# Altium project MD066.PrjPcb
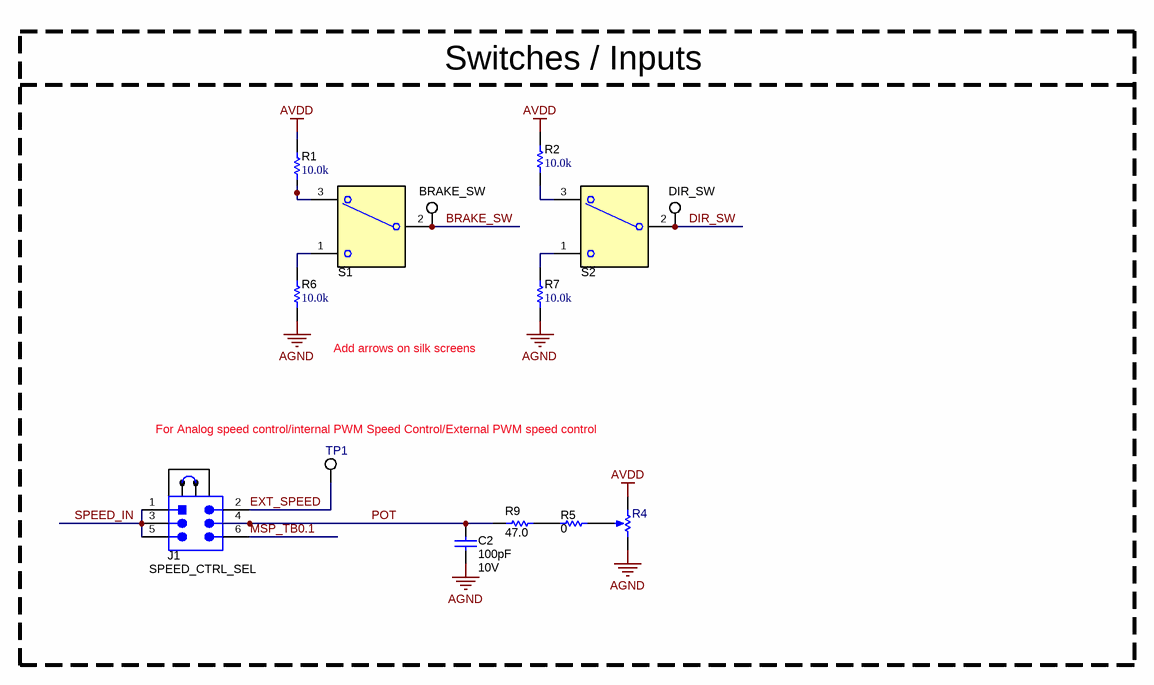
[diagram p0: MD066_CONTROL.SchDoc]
CopyrightYear: 2022; PCB_Layout: Vishnu Balaraj; PCB_Rev: A1; PRJ_Customer: Public Release; PRJ_Engineer: Vishnu Balaraj; PRJ_Number: MD066; PRJ_Title: MCx8317AEVM; ProjectVariant: EVM_Orderable; SCH_Rev: A1; TechSupport: http://www.ti.com/support; TID: N/A
5 sheets, 159 parts. Net scope: global (net labels, ports and power ports of the same name join across sheets).
Board file: MD066.PcbDoc
Sheets:
  MD066_CONTROL.SchDoc
  MD066_DRIVER.SchDoc
  MD066_HARDWARE.SchDoc
  MD066_INTERFACE.SchDoc
  MD066_POWER_AND_CONNECTORS.SchDoc

## Sheet MD066_CONTROL.SchDoc
size 431 x 279 mm; Date: Not shown in title block; ApprovedBy: Not shown in title block; CheckedBy: Not shown in title block; Author: Not shown in title block; CompanyName: Not shown in title block; Engineer: Not shown in title block; Organization: Not shown in title block; Address1: Not shown in title block; Address2: Not shown in title block; Address3: Not shown in title block; Address4: Not shown in title block; DocumentNumber: 1; Revision: Use project parameter SCH_Rev; SheetNumber: 2; SheetTotal: 5; PageSetup: Record=PageOptions¦CenterHorizontal=True¦CenterVertical=True¦PrintScale=1.00¦XCorrection=1.00¦YCorrection=1.00¦PrintKind=0¦BorderSize=5000000¦LeftOffset=0¦BottomOffset=0¦Orientation=2¦PaperLength=1000¦PaperWidth=1000¦Scale=100¦PaperSource=15¦PrintQuality=600¦MediaType=1¦DitherType=10¦PaperKind=Letter¦PrintScaleMode=1

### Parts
C2  Cap_F: 100pF  VDC_V: 10V  [0603]  (hidden comment: 0603ZC101KAT2A)
J1  SPEED_CTRL_SEL  [TSW-103-07-G-D]
R1  ValueDisplayed: 10.0k  [0603]  (hidden comment: RNCF0603TKY10K0)
R2  ValueDisplayed: 10.0k  [0603]  (hidden comment: RNCF0603TKY10K0)
R4  3352T-1-253LF  [Bourns_3352T]  (value not drawn)
R5  ValueDisplayed: 0  [0603L]  (hidden comment: ERJ-3GEY0R00V)
R6  ValueDisplayed: 10.0k  [0603]  (hidden comment: RNCF0603TKY10K0)
R7  ValueDisplayed: 10.0k  [0603]  (hidden comment: RNCF0603TKY10K0)
R9  ValueDisplayed: 47.0  [0603]  (hidden comment: RT0603BRD0747RL)
S1  SW_SPDT_COM2_1_3  [SW_B12AP]  (value not drawn)
S2  SW_SPDT_COM2_1_3  [SW_B12AP]  (value not drawn)
SH-J1  SNT-100-BK-G  [SNT-100-BK-G]  (value not drawn)
TP1  EXT_SPEED  [Keystone5002]  (value not drawn)
TP2  BRAKE_SW  [Keystone5002]
TP3  DIR_SW  [Keystone5002]

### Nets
AGND: C2.2 R4.3(CW) R6.1 R7.1
AVDD: R1.2 R2.2 R4.1(CCW)
BRAKE_SW: S1.2(COM) TP2.1
DIR_SW: S2.2(COM) TP3.1
EXT_SPEED: J1.2 TP1.1
MSP_TB0.1: J1.6
POT: C2.1 J1.4 R9.1
SPEED_IN: J1.1 J1.3 J1.5
NetR1_1: R1.1 S1.3
NetR2_1: R2.1 S2.3
NetR4_2: R4.2(WIPER) R5.2
NetR5_1: R5.1 R9.2
NetR6_2: R6.2 S1.1
NetR7_2: R7.2 S2.1

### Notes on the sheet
- Switches / Inputs
- Add arrows on silk screens
- For Analog speed control/internal PWM Speed Control/External PWM speed control

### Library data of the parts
C2 = CMP-0006812-1: CAP, CERM, 100 pF, 10 V, +/- 10%, X7R, 0603; Manufacturer: AVX; TaMin_C: -55°C; Polarized: N; SizeAreaWB_mm2: 4.68; Value1: Unknown; U/M: EA; Value: 100pF; TaMax_C: 125°C; SizeZ_mm: 1; SizeX_mm: 1.6; SizeY_mm: 0.8; SizeArea_mm2: 1.28; AEC Category: Q200
J1 = CMP-0075406-2: Header, 100mil, 3x2, Gold, TH; Manufacturer: Samtec; Pitch_mm: 2.54; Gender: Male; Shrouded: N; Row_Count: 2; Current_A: 6.3A; Voltage_V: 550V; Cert_CSA: Y; Green_Lifecycle: Active; Green_REACh: Passed
R1 R2 R6 R7 = CMP-0023626-2: RES, 10.0 k, 0.01%, 0.063 W, 0603; Manufacturer: Stackpole Electronics Inc; Power_W: 63mW; TempCo: 5 ppm/C; Value_Code: 10k0; U/M: EA; Value: 10.0k; Res_ohm: 10k; SizeX_mm: 1.6; SizeY_mm: 0.8; SizeZ_mm: 1; Value2: 0.063W; SizeArea_mm2: 1.28; VDC_V: 50V; AEC Category: Q200
R4 = CMP-0001776-2: Trimmer Potentiometer, 25kohm, 0.5W, TH; Manufacturer: Bourns
R5 = CMP-0025874-4: RES, 0, 5%, 0.1 W, AEC-Q200 Grade 0, 0603; Manufacturer: Panasonic; Power_W: 100mW; TempCo: 600 ppm/C; Value_Code: 0000; Value: 0; EIA_Code: E24; SizeX_mm: 1.6; SizeY_mm: 0.8; SizeZ_mm: 1; Value2: 0.1W; SizeArea_mm2: 1.28; AEC Qualified: Y; VDC_V: 50V; AEC Category: Q200; SizeAreaWB_mm2: 4.68
R9 = CMP-0024269-1: RES, 47.0, 0.1%, 0.1 W, 0603; Manufacturer: Yageo America; Power_W: 100mW; TempCo: 25 ppm/C; Value_Code: 47R0; U/M: EA; Value: 47.0; EIA_Code: E192; Res_ohm: 47; SizeX_mm: 1.6; SizeY_mm: 0.8; SizeZ_mm: 1; Value2: 0.1W; SizeArea_mm2: 1.28; VDC_V: 75V; AEC Category: Q200
S1 S2 = CMP-0002155-2: SWITCH TOGGLE SPDT 0.4VA 28V; PartNumber: B12AP; Manufacturer: NKK Switches; SwitchFunction: On-On; PositionCount: 2; CurrentRating_mA: 100A
SH-J1 = CMP-0003623-3: Shunt, 100mil, Gold plated, Black; Alternate PartNumber: 969102-0000-DA; Manufacturer: Samtec; Alternate Manufacturer: 3M; Value: 1x2
TP1-TP3 = CMP-0055139-1: Test Point, Miniature, White, TH; Manufacturer: Keystone; CNHeader: FALSE; Green_Lifecycle: Active; Green_REACh: Passed; ContactFinish: Silver; CT: TRUE

## Sheet MD066_DRIVER.SchDoc
size 431 x 279 mm; Date: Not shown in title block; ApprovedBy: Not shown in title block; CheckedBy: Not shown in title block; Author: Not shown in title block; CompanyName: Not shown in title block; Engineer: Not shown in title block; Organization: Not shown in title block; Address1: Not shown in title block; Address2: Not shown in title block; Address3: Not shown in title block; Address4: Not shown in title block; DocumentNumber: 2; Revision: Use project parameter SCH_Rev; SheetNumber: 3; SheetTotal: 5; PageSetup: Record=PageOptions¦CenterHorizontal=True¦CenterVertical=True¦PrintScale=1.00¦XCorrection=1.00¦YCorrection=1.00¦PrintKind=0¦BorderSize=5000000¦LeftOffset=0¦BottomOffset=0¦Orientation=2¦PaperLength=1000¦PaperWidth=1000¦Scale=100¦PaperSource=15¦PrintQuality=600¦MediaType=1¦DitherType=10¦PaperKind=Letter¦PrintScaleMode=1
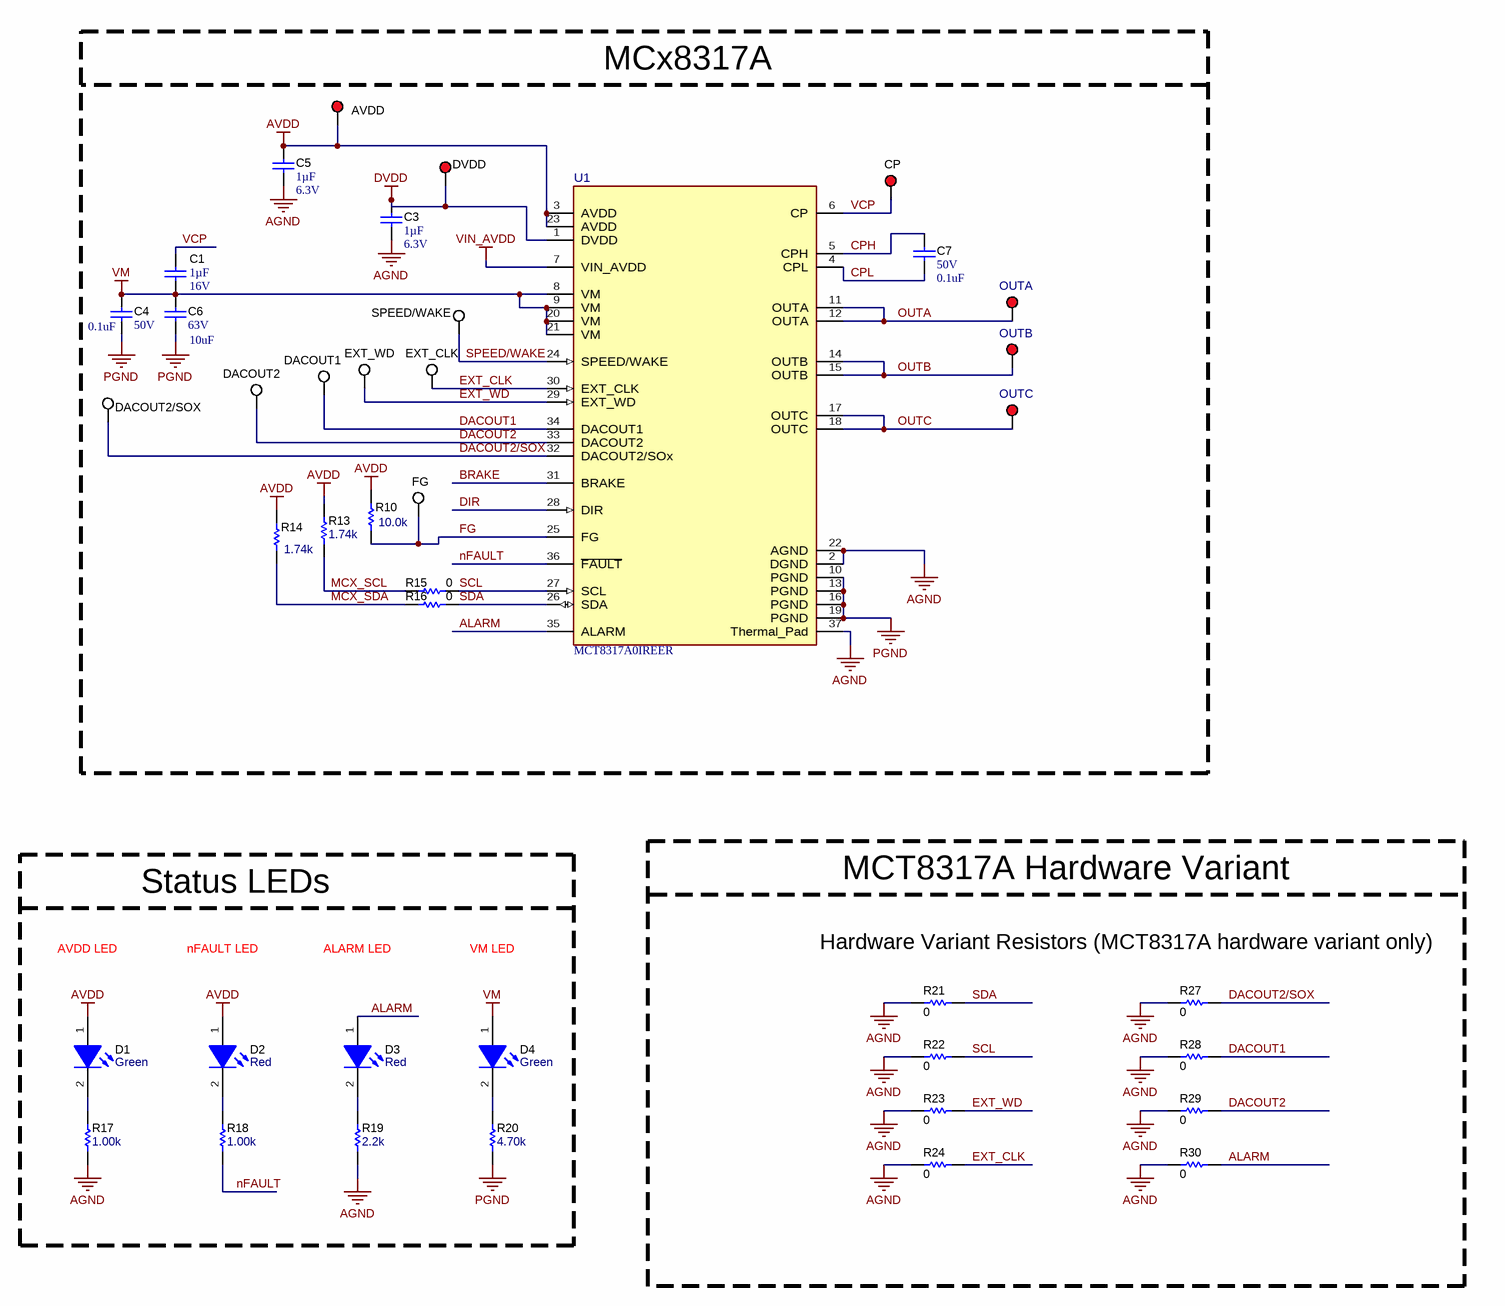
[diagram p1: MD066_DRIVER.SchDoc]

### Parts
C1  Cap_F: 1µF  VDC_V: 16V  [0603L]  (hidden comment: EMK107B7105KAHT)
C3  Cap_F: 1µF  VDC_V: 6.3V  [0603L]  (hidden comment: C0603C105K9RACAUTO)
C4  VDC_V: 50V  ValueDisplayed: 0.1uF  [0402]  (hidden comment: C1005X6S1H104K050BB)
C5  Cap_F: 1µF  VDC_V: 6.3V  [0603L]  (hidden comment: C0603C105K9RACAUTO)
C6  VDC_V: 63V  ValueDisplayed: 10uF  [1210_270]  (hidden comment: GRM32ER71J106KA12L)
C7  VDC_V: 50V  ValueDisplayed: 0.1uF  [0402]  (hidden comment: C1005X6S1H104K050BB)
D1  value Green  [LTST-C170KGKT_Green]  (hidden comment: AVDD)
D2  value Red  [LED_LTST-C170_Red]  (hidden comment: nFAULT)
D3  value Red  [LED_LTST-C170_Red]  (hidden comment: ALARM)
D4  value Green  [LTST-C170KGKT_Green]  (hidden comment: LTST-C170KGKT)
R10  ValueDisplayed: 10.0k  [0603]  (hidden comment: RCG060310K0FKEA)
R13  ValueDisplayed: 1.74k  [0603]  (hidden comment: RT0603DRE071K74L)
R14  ValueDisplayed: 1.74k  [0603]  (hidden comment: RT0603DRE071K74L)
R15  ValueDisplayed: 0  [0603L]  (hidden comment: ERJ-3GEY0R00V)
R16  ValueDisplayed: 0  [0603L]  (hidden comment: ERJ-3GEY0R00V)
R17  ValueDisplayed: 1.00k  [0603]  (hidden comment: RC0603FR-071KL)
R18  ValueDisplayed: 1.00k  [0603]  (hidden comment: RC0603FR-071KL)
R19  ValueDisplayed: 2.2k  [0603]  (hidden comment: ERJ-3GEYJ222V)
R20  ValueDisplayed: 4.70k  [0603L]  (hidden comment: RT0603BRD074K7L)
R21  ValueDisplayed: 0  [0603L]  (hidden comment: ERJ-3GEY0R00V)
R22  ValueDisplayed: 0  [0603L]  (hidden comment: ERJ-3GEY0R00V)
R23  ValueDisplayed: 0  [0603L]  (hidden comment: ERJ-3GEY0R00V)
R24  ValueDisplayed: 0  [0603L]  (hidden comment: ERJ-3GEY0R00V)
R27  ValueDisplayed: 0  [0603L]  (hidden comment: ERJ-3GEY0R00V)
R28  ValueDisplayed: 0  [0603L]  (hidden comment: ERJ-3GEY0R00V)
R29  ValueDisplayed: 0  [0603L]  (hidden comment: ERJ-3GEY0R00V)
R30  ValueDisplayed: 0  [0603L]  (hidden comment: ERJ-3GEY0R00V)
TP5  OUTA  [Keystone5000]
TP6  OUTB  [Keystone5000]
TP7  EXT_WD  [Keystone5002]
TP8  EXT_CLK  [Keystone5002]
TP9  OUTC  [Keystone5000]
TP11  AVDD  [Keystone5000]
TP12  DVDD  [Keystone5000]
TP13  CP  [Keystone5000]
TP14  SPEED/WAKE  [Keystone5002]
TP15  DACOUT1  [Keystone5002]
TP16  DACOUT2  [Keystone5002]
TP17  DACOUT2/SOX  [Keystone5002]
TP35  FG  [Keystone5002]
U1  MCT8317A0IREER  [REE0036A-MFG]

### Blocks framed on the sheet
MCx8317A: C1 C3-C7 R10 R13-R16 TP5-TP9 TP11-TP17 TP35 U1
Status LEDs: D1-D4 R17-R20
MCT8317A Hardware Variant: R21-R24 R27-R30

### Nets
AGND: C3.1 C5.1 R17.1 R19.1 R21.2 R22.2 R23.2 R24.2 R27.2 R28.2 R29.2 R30.2 U1.2(DGND) U1.22(AGND) U1.37(Thermal_Pad)
AVDD: C5.2 D1.1(A) D2.1(A) R10.2 R13.2 R14.2 TP11.1 U1.3(AVDD) U1.23(AVDD)
DVDD: C3.2 TP12.1 U1.1(DVDD)
PGND: C4.2 C6.2 R20.1 U1.10(PGND) U1.13(PGND) U1.16(PGND) U1.19(PGND)
VIN_AVDD: U1.7(VIN_AVDD)
VM: C1.2 C4.1 C6.1 D4.1(A) U1.8(VM) U1.9(VM) U1.20(VM) U1.21(VM)
ALARM: D3.1(A) R30.1 U1.35(ALARM)
BRAKE: U1.31(BRAKE)
CPH: C7.1 U1.5(CPH)
CPL: C7.2 U1.4(CPL)
DACOUT1: R28.1 TP15.1 U1.34(DACOUT1)
DACOUT2: R29.1 TP16.1 U1.33(DACOUT2)
DACOUT2/SOX: R27.1 TP17.1 U1.32(DACOUT2/SOx)
DIR: U1.28(DIR)
EXT_CLK: R24.1 TP8.1 U1.30(EXT_CLK)
EXT_WD: R23.1 TP7.1 U1.29(EXT_WD)
FG: R10.1 TP35.1 U1.25(FG)
MCX_SCL: R13.1 R15.1
MCX_SDA: R14.1 R16.1
nFAULT: R18.1 U1.36(~{FAULT})
OUTA: TP5.1 U1.11(OUTA) U1.12(OUTA)
OUTB: TP6.1 U1.14(OUTB) U1.15(OUTB)
OUTC: TP9.1 U1.17(OUTC) U1.18(OUTC)
SCL: R15.2 R22.1 U1.27(SCL)
SDA: R16.2 R21.1 U1.26(SDA)
SPEED/WAKE: TP14.1 U1.24(SPEED/WAKE)
VCP: C1.1 TP13.1 U1.6(CP)
NetD1_2: D1.2(K) R17.2
NetD2_2: D2.2(K) R18.2
NetD3_2: D3.2(K) R19.2
NetD4_2: D4.2(K) R20.2

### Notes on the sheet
- Hardware Variant Resistors (MCT8317A hardware variant only)
- AVDD LED
- nFAULT LED
- ALARM LED
- VM LED

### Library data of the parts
C1 = CMP-0080104-1: CAP, CERM, 1 µF, 16 V,+/- 10%, X7R, AEC-Q200 Grade 1, 0603; Manufacturer: Taiyo Yuden; SizeAreaWB_mm2: 4.68; SizeArea_mm2: 1.28; AEC Qualified: Y; AEC Category: Q200; Value: 1uF; TaMax_C: 125°C; SizeZ_mm: 1; Polarized: N; TaMin_C: -55°C; SizeY_mm: 0.8; U/M: EA; SizeX_mm: 1.6; Cap_Case: 0603
C3 C5 = CMP-0086190-1: CAP, CERM, 1 µF, 6.3 V,+/- 10%, X7R, AEC-Q200 Grade 1, 0603; Manufacturer: Kemet; SizeArea_mm2: 1.28; Cap_Case: 0603; SizeY_mm: 0.8; AEC Category: Q200; AEC Qualified: Y; TaMax_C: 125°C; SizeZ_mm: 1; SizeX_mm: 1.6; Polarized: N; Value: 1uF; SizeAreaWB_mm2: 4.68; TaMin_C: -55°C; U/M: EA
C4 C7 = CMP-0006289-1: CAP, CERM, 0.1 uF, 50 V, +/- 10%, X6S, 0402; Manufacturer: TDK; TaMin_C: -55°C; ESR_ohm: 0.039064; Polarized: N; SizeAreaWB_mm2: 3; Value1: 0.039064 ohm; U/M: EA; Value: 0.1uF; TaMax_C: 105°C; SizeZ_mm: 0.6; SizeX_mm: 1; SizeY_mm: 0.5; Cap_F: 100nF; IRMS_A: 814.669mA; AEC Category: Q200
C6 = CMP-0009229-1: CAP, CERM, 10 uF, 63 V, +/- 10%, X7R, 1210; Manufacturer: MuRata; TaMin_C: -55°C; Polarized: N; SizeAreaWB_mm2: 14.7; Value1: Unknown; U/M: EA; Value: 10uF; TaMax_C: 125°C; SizeZ_mm: 2.7; SizeX_mm: 3.2; SizeY_mm: 2.5; Cap_Case: 1210; SizeArea_mm2: 8; Cap_F: 10µF; AEC Category: Q200
D1 = CMP-0002888-2: LED, Green, SMD; Manufacturer: Lite-On; PartNumber: LTST-C170KGKT; Io_A: 20mA; Value1: W; Vf_V: 2V; Type: AlInGaP
D2 D3 = CMP-0002829-3: LED, Red, SMD; Manufacturer: Lite-On; PartNumber: LTST-C170KRKT; Io_A: 20mA; SizeAreaWB_mm2: 6.75; Value1: W; SizeZ_mm: 1.2; SizeX_mm: 2; SizeY_mm: 1.25; Vf_V: 2V; SizeArea_mm2: 2.5; Type: AlInGaP
D4 = CMP-0002888-2: LED, Green, SMD; Manufacturer: Lite-On; Io_A: 20mA; Value1: W; Vf_V: 2V; Type: AlInGaP
R10 = CMP-0023337-3: RES, 10.0 k, 1%, 0.1 W, 0603; Manufacturer: Vishay Draloric; Power_W: 100mW; TempCo: 100 ppm/C; Value_Code: 10k0; U/M: EA; Value: 10.0k; EIA_Code: E96; Res_ohm: 10k; SizeX_mm: 1.6; SizeY_mm: 0.8; SizeZ_mm: 1; Value2: 0.1W; SizeArea_mm2: 1.28; AEC Qualified: N; VDC_V: 75V; AEC Category: Q200
R13 R14 = CMP-0024840-3: RES, 1.74 k, 0.5%, 0.1 W, 0603; Manufacturer: Yageo America; Power_W: 100mW; TempCo: 50 ppm/C; Value_Code: 1k74; U/M: EA; Value: 1.74k; EIA_Code: E192; SizeX_mm: 1.6; SizeY_mm: 0.8; SizeZ_mm: 1; Value2: 0.1W; SizeArea_mm2: 1.28; VDC_V: 75V; AEC Category: Q200
R15 R16 R21-R24 R27-R30 = CMP-0025874-4: as R5 on sheet MD066_CONTROL
R17 R18 = CMP-0022895-5: RES, 1.00 k, 1%, 0.1 W, 0603; Manufacturer: Yageo; Power_W: 100mW; TempCo: 100 ppm/C; Value_Code: 1k00; Value: 1.00k; EIA_Code: E96; Res_ohm: 1k; SizeX_mm: 1.6; SizeY_mm: 0.8; SizeZ_mm: 1; Value2: 0.1W; SizeArea_mm2: 1.28; AEC Qualified: N; VDC_V: 75V; AEC Category: Q200; SizeAreaWB_mm2: 4.68
R19 = CMP-0025879-1: RES, 2.2 k, 5%, 0.1 W, AEC-Q200 Grade 0, 0603; Manufacturer: Panasonic; Power_W: 100mW; TempCo: 200 ppm/C; Value_Code: 2k20; U/M: EA; Value: 2.2k; EIA_Code: E24; SizeX_mm: 1.6; SizeY_mm: 0.8; SizeZ_mm: 1; Value2: 0.1W; SizeArea_mm2: 1.28; AEC Qualified: Y; VDC_V: 75V; AEC Grade: 0; AEC Category: Q200
R20 = CMP-0024300-2: RES, 4.70 k, 0.1%, 0.1 W, 0603; Manufacturer: Yageo America; Power_W: 100mW; TempCo: 25 ppm/C; Value_Code: 4k70; U/M: EA; Value: 4.70k; EIA_Code: E192; Res_ohm: 4.7k; SizeX_mm: 1.6; SizeY_mm: 0.8; SizeZ_mm: 1; Value2: 0.1W; SizeArea_mm2: 1.28; VDC_V: 75V; AEC Category: Q200
TP5 TP6 TP9 = CMP-0055137-1: Test Point, Miniature, Red, TH; PartNumber: 5000; Manufacturer: Keystone; ContactFinish: Silver; CNHeader: FALSE; CT: TRUE; Green_Lifecycle: Active; Green_REACh: Passed
TP7 TP8 TP14-TP17 TP35 = CMP-0055139-1: as TP1 on sheet MD066_CONTROL
TP11-TP13 = CMP-0055137-1: Test Point, Miniature, Red, TH; Manufacturer: Keystone; CNHeader: FALSE; Green_Lifecycle: Active; Green_REACh: Passed; ContactFinish: Silver; CT: TRUE
U1 = CMP-0096865-1: High Speed Sensorless Trapezoidal Control Integrated FET BLDC Driver; Manufacturer: Texas Instruments; Max Supply Voltage: 20V; TJmax_C: +150°C; Nominal Supply Current: 25mA; SizeZ_mm: 0.8mm; AEC Qualified: No; Motor Type: Brushless DC; Standoff Height: 0mm; TaMax_C: +125°C; Min Supply Voltage: 4.5V; Number Of Outputs: 3; TaMin_C: -40°C; Switching Frequency: 100kHz

## Sheet MD066_HARDWARE.SchDoc
size 431 x 279 mm; Date: Not shown in title block; ApprovedBy: Not shown in title block; CheckedBy: Not shown in title block; Author: Not shown in title block; CompanyName: Not shown in title block; Engineer: Not shown in title block; Organization: Not shown in title block; Address1: Not shown in title block; Address2: Not shown in title block; Address3: Not shown in title block; Address4: Not shown in title block; DocumentNumber: 3; Revision: Use project parameter SCH_Rev; SheetNumber: 5; SheetTotal: 5; PageSetup: Record=PageOptions¦CenterHorizontal=True¦CenterVertical=True¦PrintScale=1.00¦XCorrection=1.00¦YCorrection=1.00¦PrintKind=0¦BorderSize=5000000¦LeftOffset=0¦BottomOffset=0¦Orientation=2¦PaperLength=1000¦PaperWidth=1000¦Scale=100¦PaperSource=15¦PrintQuality=600¦MediaType=1¦DitherType=10¦PaperKind=Letter¦PrintScaleMode=1
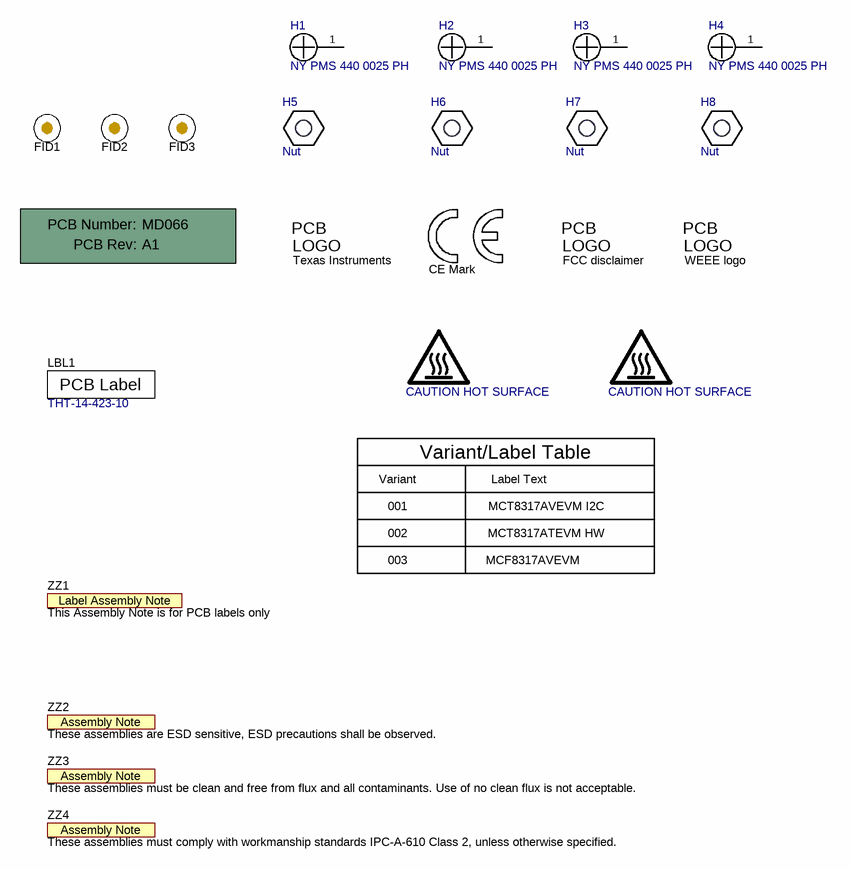
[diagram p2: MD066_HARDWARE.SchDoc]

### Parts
!PCB1  Printed Circuit Board  (value not drawn)  (mechanical)
FID1  Fiducial  [Fiducial10-20]  (value not drawn)
FID2  Fiducial  [Fiducial10-20]  (value not drawn)
FID3  Fiducial  [Fiducial10-20]  (value not drawn)
H1  NY PMS 440 0025 PH  [NY PMS 440 0025 PH]
H2  NY PMS 440 0025 PH  [NY PMS 440 0025 PH]
H3  NY PMS 440 0025 PH  [NY PMS 440 0025 PH]
H4  NY PMS 440 0025 PH  [NY PMS 440 0025 PH]
H5  Nut  [Keystone_1902C]
H6  Nut  [Keystone_1902C]
H7  Nut  [Keystone_1902C]
H8  Nut  [Keystone_1902C]
LBL1  THT-14-423-10  [Label_650x200]
Logo1  CE Mark  [CE_Mark_5mm]  (no BOM)
Logo2  Texas Instruments  [TI_Stacked_Overlay_Small]  (no BOM)
Logo3  FCC disclaimer  [FCC_disclaimer]  (no BOM)
Logo4  WEEE logo  [WEEE_Minimum]  (no BOM)
LOGO5  CAUTION HOT SURFACE  [IEC_HotSurface_Small]  (no BOM)
LOGO6  CAUTION HOT SURFACE  [IEC_HotSurface_Small]  (no BOM)
ZZ1  This Assembly Note is for PCB labels only  [AssemblyNoteLabel]  (no BOM)
ZZ2  These assemblies are ESD sensitive, ESD precautions shall be observed.  [AssemblyNote]  (no BOM)
ZZ3  These assemblies must be clean and free from flux and all contaminants. Use of no clean flux is not acceptable.  [AssemblyNote]  (no BOM)
ZZ4  These assemblies must comply with workmanship standards IPC-A-610 Class 2, unless otherwise specified.  [AssemblyNote]  (no BOM)

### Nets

Not connected (* = marked no-connect by the designer): H1 1; H2 1; H3 1; H4 1

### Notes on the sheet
- Variant
- Variant/Label Table
- Label Text
- 001
- 002
- MCT8317AVEVM I2C
- MCT8317ATEVM HW
- 003
- MCF8317AVEVM

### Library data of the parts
!PCB1 = CMP-0003618-2: Manufacturer: Any; PartNumber: MD066
FID1-FID3 = CMP-0077181-1: Fiducial mark.  There is nothing to buy or mount.
H1-H4 = CMP-0003617-1: Machine Screw, Round, #4-40 x 1/4, Nylon, Philips panhead; Manufacturer: B&F Fastener Supply; CompType: Hardware
H5-H8 = CMP-0003610-1: Standoff, Hex, 0.5"L #4-40 Nylon; Manufacturer: Keystone; PartNumber: 1902C; CompType: Hardware
LBL1 = CMP-0003625-1: Manufacturer: Brady
Logo1 = CMP-0074844-1: SymbolCreator: a0412235
Logo2 = CMP-0074838-1: Texas Instrument Corporate Signature; SymbolCreator: a0412235; Lib Reference: TI_Logo; Library Reference: Logo
Logo3 = CMP-0074847-1: FCC_disclaimer; Library Reference: Logo
Logo4 = CMP-0074769-1
LOGO5 LOGO6 = CMP-0074837-1: IEC 61010-1 Hot Surface Warning; SymbolCreator: a0412235
ZZ1 = CMP-0003616-3
ZZ2 = CMP-0077236-1
ZZ3 = CMP-0077237-1
ZZ4 = CMP-0077238-1

## Sheet MD066_INTERFACE.SchDoc
size 431 x 279 mm; Date: Not shown in title block; ApprovedBy: Not shown in title block; CheckedBy: Not shown in title block; Author: Not shown in title block; CompanyName: Not shown in title block; Engineer: Not shown in title block; Organization: Not shown in title block; Address1: Not shown in title block; Address2: Not shown in title block; Address3: Not shown in title block; Address4: Not shown in title block; DocumentNumber: 4; Revision: Use project parameter SCH_Rev; SheetNumber: 1; SheetTotal: 5; PageSetup: Record=PageOptions¦CenterHorizontal=True¦CenterVertical=True¦PrintScale=1.00¦XCorrection=1.00¦YCorrection=1.00¦PrintKind=0¦BorderSize=5000000¦LeftOffset=0¦BottomOffset=0¦Orientation=2¦PaperLength=1000¦PaperWidth=1000¦Scale=100¦PaperSource=15¦PrintQuality=600¦MediaType=1¦DitherType=10¦PaperKind=Letter¦PrintScaleMode=1
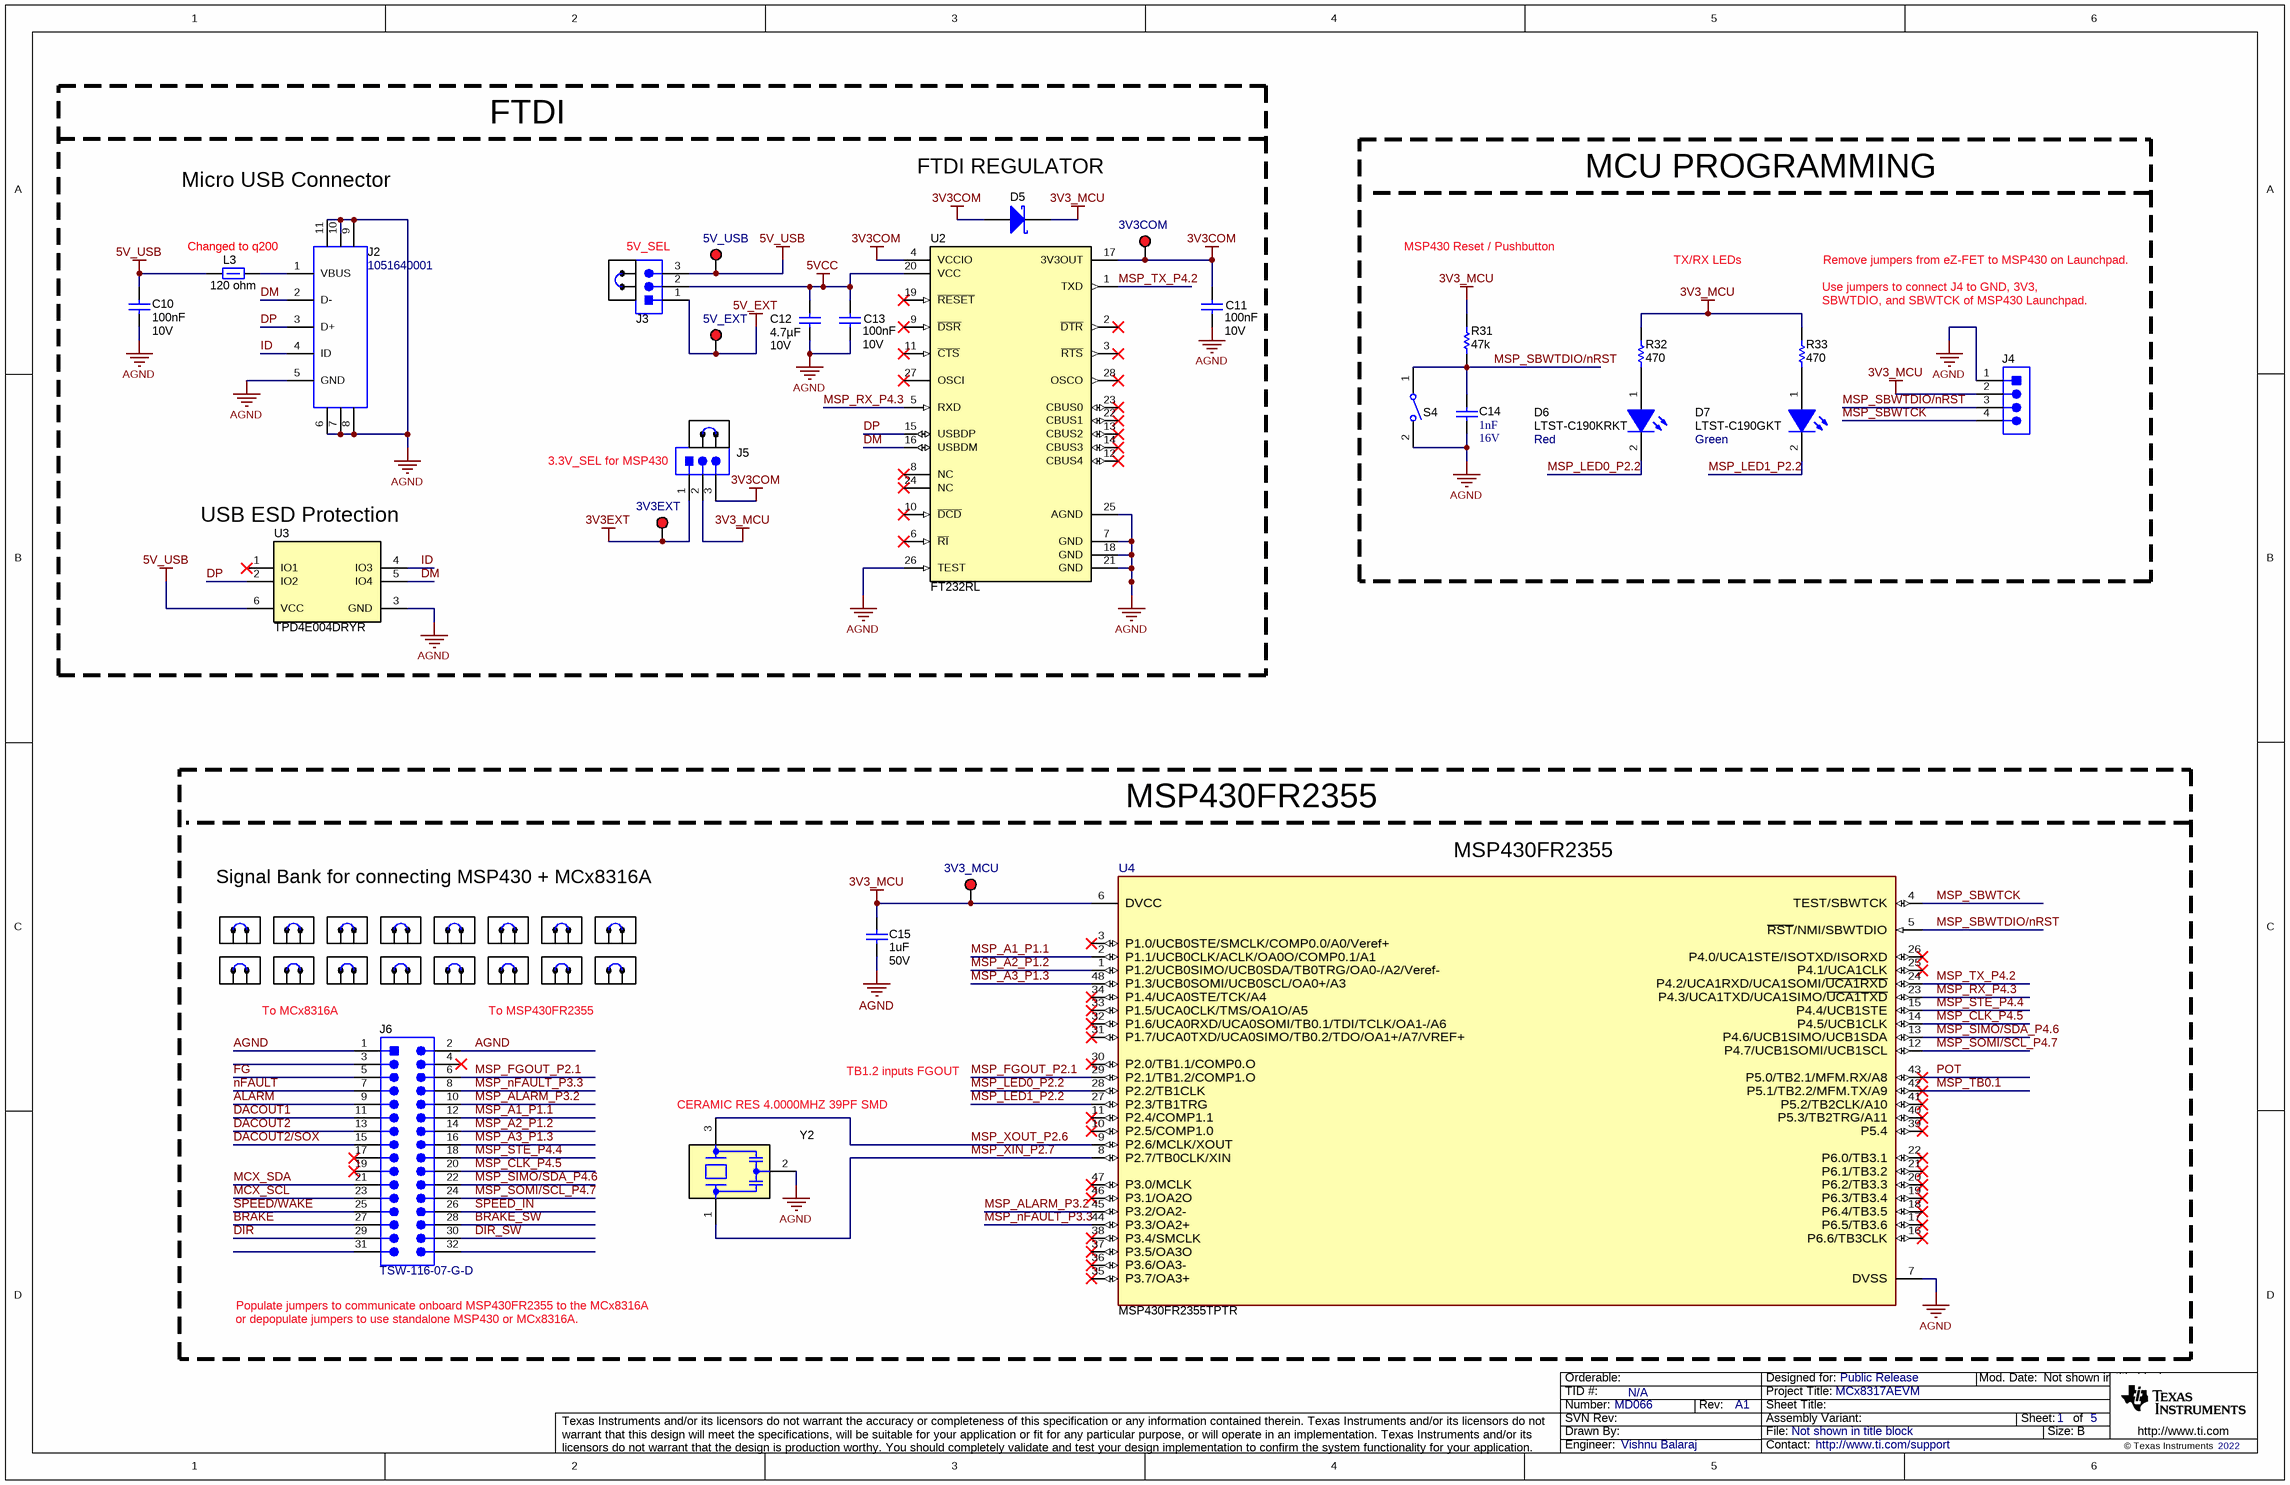
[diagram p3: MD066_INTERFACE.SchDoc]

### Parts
C10  Cap_F: 100nF  VDC_V: 10V  [0603L]  (hidden comment: 0603ZC104KAT2A)
C11  Cap_F: 100nF  VDC_V: 10V  [0603L]  (hidden comment: 0603ZC104KAT2A)
C12  Cap_F: 4.7µF  VDC_V: 10V  [0603L]  (hidden comment: GRM188Z71A475ME15D)
C13  Cap_F: 100nF  VDC_V: 10V  [0603L]  (hidden comment: 0603ZC104KAT2A)
C14  Cap_F: 1nF  VDC_V: 16V  [0603L]  (hidden comment: 885012206034)
C15  ValueDisplayed: 1uF  VDC_V: 50V  [0805L]  (hidden comment: 885012207103)
D5  BAT165E6327HTSA1  [SOD-323]  (value not drawn)
D6  LTST-C190KRKT  value Red  [LED_LTST-C190_Red]
D7  LTST-C190GKT  value Green  [LED_LTST-C190]
J2  1051640001  [Molex_1051640001]
J3  Header_3x1  [PBC03SAAN]  (value not drawn)
J4  TSW-104-07-G-S  [TSW-104-07-G-S]  (value not drawn)
J5  Header_3x1  [PBC03SAAN]  (value not drawn)
J6  TSW-116-07-G-D  [TSW-116-07-G-D]
L3  DCR_ohm: 120 ohm  [0603L]  (hidden comment: BLM18SG121TZ1D)
R31  ValueDisplayed: 47k  [0603L]  (hidden comment: RC0603JR-0747KL)
R32  ValueDisplayed: 470  [0603L]  (hidden comment: RC0603JR-07470RL)
R33  ValueDisplayed: 470  [0603L]  (hidden comment: RC0603JR-07470RL)
S4  SW_SPST-single  [SW_434121025816]  (value not drawn)
SH-J2  SNT-100-BK-G  [SNT-100-BK-G]  (value not drawn)
SH-J3  SNT-100-BK-G  [SNT-100-BK-G]  (value not drawn)
SH-J4  SNT-100-BK-G  [SNT-100-BK-G]  (value not drawn)
SH-J5  SNT-100-BK-G  [SNT-100-BK-G]  (value not drawn)
SH-J6  SNT-100-BK-G  [SNT-100-BK-G]  (value not drawn)
SH-J7  SNT-100-BK-G  [SNT-100-BK-G]  (value not drawn)
SH-J8  SNT-100-BK-G  [SNT-100-BK-G]  (value not drawn)
SH-J9  SNT-100-BK-G  [SNT-100-BK-G]  (value not drawn)
SH-J10  SNT-100-BK-G  [SNT-100-BK-G]  (value not drawn)
SH-J11  SNT-100-BK-G  [SNT-100-BK-G]  (value not drawn)
SH-J12  SNT-100-BK-G  [SNT-100-BK-G]  (value not drawn)
SH-J13  SNT-100-BK-G  [SNT-100-BK-G]  (value not drawn)
SH-J14  SNT-100-BK-G  [SNT-100-BK-G]  (value not drawn)
SH-J15  SNT-100-BK-G  [SNT-100-BK-G]  (value not drawn)
SH-J16  SNT-100-BK-G  [SNT-100-BK-G]  (value not drawn)
SH-J17  SNT-100-BK-G  [SNT-100-BK-G]  (value not drawn)
SH-J18  SNT-100-BK-G  [SNT-100-BK-G]  (value not drawn)
SH-J19  SNT-100-BK-G  [SNT-100-BK-G]  (value not drawn)
TP18  3V3COM  [Keystone5000]
TP19  5V_USB  [Keystone5000]
TP20  5V_EXT  [Keystone5000]
TP21  3V3EXT  [Keystone5000]
TP22  3V3_MCU  [Keystone5000]
U2  FT232RL  [SSOP28_N]
U3  TPD4E004DRYR  [DRY0006A]
U4  MSP430FR2355TPTR  [PT0048A-MFG]
Y2  CSTCR4M00G55B-R0  [Murata_CSTCR_G]  (value not drawn)

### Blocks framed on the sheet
FTDI: C10-C13 D5 J2 J3 J5 L3 SH-J2 SH-J3 TP18-TP21 U2 U3
MCU PROGRAMMING: C14 D6 D7 J4 R31-R33 S4
MSP430FR2355: C15 J6 SH-J4-SH-J19 TP22 U4 Y2

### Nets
3V3_MCU: C15.1 D5.1(K) J4.2 J5.2 R31.2 R32.2 R33.2 TP22.1 U4.6(DVCC)
3V3COM: C11.1 D5.2(A) J5.3 TP18.1 U2.4(VCCIO) U2.17(3V3OUT)
3V3EXT: J5.1 TP21.1
5V_EXT: J3.1 TP20.1
5V_USB: C10.1 J3.3 L3.1 TP19.1 U3.6(VCC)
5VCC: C12.2 C13.1 J3.2 U2.20(VCC)
AGND: C10.2 C11.2 C12.1 C13.2 C14.2 C15.2 J2.5(GND) J2.6 J2.7 J2.8 J2.9 J2.10 J2.11 J4.1 J6.1 J6.2 S4.2 U2.7(GND) U2.18(GND) U2.21(GND) U2.25(AGND) U2.26(TEST) U3.3(GND) U4.7(DVSS) Y2.2(GND)
ALARM: J6.9
BRAKE: J6.27
BRAKE_SW: J6.28
DACOUT1: J6.11
DACOUT2: J6.13
DACOUT2/SOX: J6.15
DIR: J6.29
DIR_SW: J6.30
DM: J2.2(D-) U2.16(USBDM) U3.5(IO4)
DP: J2.3(D+) U2.15(USBDP) U3.2(IO2)
FG: J6.5
ID: J2.4(ID) U3.4(IO3)
MCX_SCL: J6.23
MCX_SDA: J6.21
MSP_A1_P1.1: J6.12 U4.2(P1.1/UCB0CLK/ACLK/OA0O/COMP0.1/A1)
MSP_A2_P1.2: J6.14 U4.1(P1.2/UCB0SIMO/UCB0SDA/TB0TRG/OA0-/A2/Veref-)
MSP_A3_P1.3: J6.16 U4.48(P1.3/UCB0SOMI/UCB0SCL/OA0+/A3)
MSP_ALARM_P3.2: J6.10 U4.45(P3.2/OA2-)
MSP_CLK_P4.5: J6.20 U4.14(P4.5/UCB1CLK)
MSP_FGOUT_P2.1: J6.6 U4.29(P2.1/TB1.2/COMP1.O)
MSP_LED0_P2.2: D6.2(K) U4.28(P2.2/TB1CLK)
MSP_LED1_P2.2: D7.2(K) U4.27(P2.3/TB1TRG)
MSP_nFAULT_P3.3: J6.8 U4.44(P3.3/OA2+)
MSP_RX_P4.3: U2.5(RXD) U4.23(P4.3/UCA1TXD/UCA1SIMO/~{UCA1TXD})
MSP_SBWTCK: J4.4 U4.4(TEST/SBWTCK)
MSP_SBWTDIO/nRST: C14.1 J4.3 R31.1 S4.1 U4.5(~{RST}/NMI/SBWTDIO)
MSP_SIMO/SDA_P4.6: J6.22 U4.13(P4.6/UCB1SIMO/UCB1SDA)
MSP_SOMI/SCL_P4.7: J6.24 U4.12(P4.7/UCB1SOMI/UCB1SCL)
MSP_STE_P4.4: J6.18 U4.15(P4.4/UCB1STE)
MSP_TB0.1: U4.42(P5.1/TB2.2/MFM.TX/A9)
MSP_TX_P4.2: U2.1(TXD) U4.24(P4.2/UCA1RXD/UCA1SOMI/~{UCA1RXD})
MSP_XIN_P2.7: U4.8(P2.7/TB0CLK/XIN) Y2.1(In)
MSP_XOUT_P2.6: U4.9(P2.6/MCLK/XOUT) Y2.3(Out)
nFAULT: J6.7
POT: U4.43(P5.0/TB2.1/MFM.RX/A8)
SPEED/WAKE: J6.25
SPEED_IN: J6.26
NetD6_1: D6.1(A) R32.1
NetD7_1: D7.1(A) R33.1
NetJ2_1: J2.1(VBUS) L3.2

Not connected (* = marked no-connect by the designer): J6 3 4* 17* 19* 31 32; U2 2(~{DTR})* 3(~{RTS})* 6(~{RI})* 8(NC)* 9(~{DSR})* 10(~{DCD})* 11(~{CTS})* 12(CBUS4)* 13(CBUS2)* 14(CBUS3)* 19(~{RESET})* 22(CBUS1)* 23(CBUS0)* 24(NC)* 27(OSCI)* 28(OSCO)*; U3 1(IO1)*; U4 3(P1.0/UCB0STE/SMCLK/COMP0.0/A0/Veref+)* 10(P2.5/COMP1.0)* 11(P2.4/COMP1.1)* 16(P6.6/TB3CLK)* 17(P6.5/TB3.6)* 18(P6.4/TB3.5)* 19(P6.3/TB3.4)* 20(P6.2/TB3.3)* 21(P6.1/TB3.2)* 22(P6.0/TB3.1)* 25(P4.1/UCA1CLK)* 26(P4.0/UCA1STE/ISOTXD/ISORXD)* 30(P2.0/TB1.1/COMP0.O)* 31(P1.7/UCA0TXD/UCA0SIMO/TB0.2/TDO/OA1+/A7/VREF+)* 32(P1.6/UCA0RXD/UCA0SOMI/TB0.1/TDI/TCLK/OA1-/A6)* 33(P1.5/UCA0CLK/TMS/OA1O/A5)* 34(P1.4/UCA0STE/TCK/A4)* 35(P3.7/OA3+)* 36(P3.6/OA3-)* 37(P3.5/OA3O)* 38(P3.4/SMCLK)* 39(P5.4)* 40(P5.3/TB2TRG/A11)* 41(P5.2/TB2CLK/A10)* 46(P3.1/OA2O)* 47(P3.0/MCLK)*

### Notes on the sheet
- (near D5) FTDI REGULATOR
- Micro USB Connector
- (near L3) Changed to q200
- 5V_SEL
- MSP430 Reset / Pushbutton
- TX/RX LEDs
- (near R33) Use jumpers to connect J4 to GND, 3V3,
- SBWTDIO, and SBWTCK of MSP430 Launchpad.
- Remove jumpers from eZ-FET to MSP430 on Launchpad.
- (near J5) 3.3V_SEL for MSP430
- (near U3) USB ESD Protection
- Signal Bank for connecting MSP430 + MCx8316A
- (near U4) MSP430FR2355
- To MCx8316A
- To MSP430FR2355
- (near Y2) CERAMIC RES 4.0000MHZ 39PF SMD
- TB1.2 inputs FGOUT
- (near J6) Populate jumpers to communicate onboard MSP430FR2355 to the MCx8316A
- or depopulate jumpers to use standalone MSP430 or MCx8316A.

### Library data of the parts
C10 C11 C13 = CMP-0006815-4: CAP, CERM, 0.1 uF, 10 V, +/- 10%, X7R, 0603; Manufacturer: AVX; TaMin_C: -55°C; Polarized: N; SizeAreaWB_mm2: 4.68; Value1: Unknown; U/M: EA; Value: 0.1uF; TaMax_C: 125°C; SizeZ_mm: 1; SizeX_mm: 1.6; SizeY_mm: 0.8; Cap_Case: 0603; SizeArea_mm2: 1.28; AEC Category: Q200
C12 = CMP-0007498-4: CAP, CERM, 4.7 uF, 10 V, +/- 20%, X7R, 0603; Manufacturer: MuRata; TaMin_C: -55°C; Polarized: N; SizeAreaWB_mm2: 4.68; Value1: Unknown; U/M: EA; Value: 4.7uF; TaMax_C: 125°C; SizeZ_mm: 1; SizeX_mm: 1.6; SizeY_mm: 0.8; Cap_Case: 0603; SizeArea_mm2: 1.28; AEC Category: Q200
C14 = CMP-0006826-4: CAP, CERM, 1000 pF, 16 V, +/- 10%, X7R, 0603; Manufacturer: Wurth Elektronik; TaMin_C: -55°C; Polarized: N; SizeAreaWB_mm2: 4.68; Value1: Unknown; U/M: EA; Value: 1000pF; TaMax_C: 125°C; SizeZ_mm: 1; SizeX_mm: 1.6; SizeY_mm: 0.8; Cap_Case: 0603; SizeArea_mm2: 1.28; AEC Category: Q200
C15 = CMP-0007696-2: CAP, CERM, 1 uF, 50 V, +/- 10%, X7R, 0805; Manufacturer: Wurth Elektronik; Polarized: N; CompType: Capacitor; Value: 1uF; U/M: EA; Cap_F: 1µF; Value1: Unknown; TaMin_C: -55°C; TaMax_C: 125°C; Cap_Case: 0805; SizeArea_mm2: 2.5; SizeAreaWB_mm2: 6.75; SizeX_mm: 2; SizeY_mm: 1.25; SizeZ_mm: 1.45; AEC Category: Q200
D5 = CMP-0028882-2: Diode, Schottky, 40 V, 0.75 A, AEC-Q101, SOD-323; Manufacturer: Infineon Technologies; Vf_V: 740mV; Value: 40V; Value1: 0.75A; Value2: 0.74V; Io_A: 750mA; TJmax_C: 150°C; AEC Category: Q101; AEC Qualified: Y; Green_Lifecycle: Not Set; Green_REACh: Incomplete; SizeArea_mm2: 3.645; SizeAreaWB_mm2: 8.695; SizeX_mm: 2.7; SizeY_mm: 1.35; SizeZ_mm: 1
D6 = CMP-0078131-2: LED, Red, SMD; Manufacturer: Lite-On; Type: AlInGaP; Ir_A: 10µA; Angle: 130; Power_TotalModule: 62.5mW; Value2: 2V; Green_Lifecycle: Not Set; Io_A: 20mA; Value1: .0625W; Green_REACh: Incomplete; Vr_V: 5V
D7 = CMP-0002827-2: LED, Green, SMD; Manufacturer: Lite-On; Io_A: 20mA; Power_TotalModule: 100mW; Value1: 0.1W; U/M: EA; Vf_V: 2.1V
J2 = CMP-0055311-1: Receptacle, USB 2.0, Micro B, 5 Position, R/A, SMT; Manufacturer: Molex; CNHeader: FALSE; Current_A: 1.8A; Gender: Female; Voltage_V: 30V; Pitch_mm: 0.65; ContactFinish: Gold; CT: TRUE; Cert_UL: Y
J3 J5 = CMP-0002334-1: Header, 100mil, 3x1, Gold, TH; Manufacturer: Sullins Connector Solutions; CNHeader: TRUE; CT: FALSE; Green_Lifecycle: Not Set; Green_REACh: Incomplete
J4 = CMP-0075409-2: Header, 100mil, 4x1, Gold, TH; Manufacturer: Samtec; Pitch_mm: 2.54; Cert_VDE: N; Gender: Male; Cert_CSA: Y; Voltage_V: 550V; Green_REACh: Passed; Current_A: 6.3A; Green_Lifecycle: Active; Row_Count: 1
J6 = CMP-0075429-1: Header, 100mil, 16x2, Gold, TH; Manufacturer: Samtec; Pitch_mm: 2.54; Cert_VDE: N; Gender: Male; Cert_CSA: Y; Voltage_V: 550V; Green_REACh: Passed; Current_A: 6.3A; CT: False; Green_Lifecycle: Active; Row_Count: 2; CNHeader: True
L3 = CMP-0084877-1: Inductor, Ferrite Bead, Ferrite, 3 A, 120 ohm, AEC-Q200 Grade 1, SMD; Manufacturer: MuRata; SizeX_mm: 1.6; AEC Grade: 1; Value2: 3A; SizeY_mm: 0.8; SizeAreaWB_mm2: 4.68; SizeArea_mm2: 1.28; AEC Qualified: Y; AEC Category: Q200
R31 = CMP-0025925-5: RES, 47 k, 5%, 0.1 W, 0603; Manufacturer: Yageo; Power_W: 100mW; TempCo: 100 ppm/C; Value_Code: 47k0; Value: 47k; EIA_Code: E24; SizeX_mm: 1.6; SizeY_mm: 0.8; SizeZ_mm: 1; Value2: 0.1W; SizeArea_mm2: 1.28; AEC Qualified: N; VDC_V: 75V; AEC Category: Q200; SizeAreaWB_mm2: 4.68
R32 R33 = CMP-0025924-5: RES, 470, 5%, 0.1 W, 0603; Manufacturer: Yageo; Power_W: 100mW; TempCo: 100 ppm/C; Value_Code: 470R; Value: 470; EIA_Code: E24; SizeX_mm: 1.6; SizeY_mm: 0.8; SizeZ_mm: 1; Value2: 0.1W; SizeArea_mm2: 1.28; AEC Qualified: N; VDC_V: 75V; AEC Category: Q200; SizeAreaWB_mm2: 4.68
S4 = CMP-0002196-2: Switch, Tactile, SPST, 12 V, SMD; PartNumber: 434121025816; Manufacturer: Wurth Elektronik; VDC_V: 12V; SwitchFunction: Off-On; PositionCount: 1; CurrentRating_mA: 50A
SH-J2-SH-J19 = CMP-0003623-3: as SH-J1 on sheet MD066_CONTROL
TP18-TP22 = CMP-0055137-1: as TP5 on sheet MD066_DRIVER
U2 = CMP-0004774-1: USB to Serial UART, SSOP28; Manufacturer: FTDI
U3 = CMP-0043115-3: 4-Channel ESD Protection Array for High-Speed Data Interfaces, DRY0006A (USON-6); Manufacturer: Texas Instruments; IO Leakage Current(nA): 1; USB High Speed: TRUE; IO Capacitance(Typ)(pF): 1.6; Eco-Plan: Green (RoHS & no Sb/Br); IEC 61000-4-2 Contact(+/- kV): 8; Breakdown Voltage(Min)(V): 6; IEC 61000-4-2 Air-Gap(+/- kV): 12; AEC Category: Q200; AEC Qualified: N; CompType: IC; SizeAreaWB_mm2: 4.9; SizeArea_mm2: 1.45; SizeX_mm: 1.0; SizeZ_mm: 0.6; Rating: Catalog
U4 = CMP-0089204-1: CPU16 MSP430™ FRAM Microcontroller IC 16-Bit 24MHz 32KB (32K x 8) FRAM 48-LQFP (7x7); Manufacturer: Texas Instruments; Memory Type: OTHER; Data Bus Width: 16bits; Number Of Spi Channels: 4; Number Of I/Os: 44; Number Of Uart Channels: 2; AEC Qualified: No; Standoff Height: 0.05mm; Ram Size: 4KBytes; TaMin_C: -40°C; Core Architecture: RISC; Number Of Adc Channels: 12; SizeZ_mm: 1.6mm; Number Of A/D Converters: 1; Memory Size: 32KBytes; TaMax_C: +105°C; TJmax_C: +115°C; Interface: I2C,SPI,UART,USART,SCI,IrDA; Min Supply Voltage: 1.8V; Max Supply Voltage: 3.6V
Y2 = CMP-0084387-1: Resonator, 4 MHz, 39 pF, AEC-Q200 Grade 1, SMD; Manufacturer: MuRata; Load Capacitance: 39 pF; AEC Qualified: Y; TaMax_C: 125°C; AEC Category: Q200; SizeArea_mm2: 9; SizeZ_mm: 1.2; Frequency_Fixed: 4MHz; SizeAreaWB_mm2: 16.5; SizeY_mm: 2; SizeX_mm: 4.5; TaMin_C: -40°C; AEC Grade: 1

## Sheet MD066_POWER_AND_CONNECTORS.SchDoc
size 431 x 279 mm; Date: Not shown in title block; ApprovedBy: Not shown in title block; CheckedBy: Not shown in title block; Author: Not shown in title block; CompanyName: Not shown in title block; Engineer: Not shown in title block; Organization: Not shown in title block; Address1: Not shown in title block; Address2: Not shown in title block; Address3: Not shown in title block; Address4: Not shown in title block; DocumentNumber: 5; Revision: Use project parameter SCH_Rev; SheetNumber: 4; SheetTotal: 5; PageSetup: Record=PageOptions¦CenterHorizontal=True¦CenterVertical=True¦PrintScale=1.00¦XCorrection=1.00¦YCorrection=1.00¦PrintKind=0¦BorderSize=5000000¦LeftOffset=0¦BottomOffset=0¦Orientation=2¦PaperLength=1000¦PaperWidth=1000¦Scale=100¦PaperSource=15¦PrintQuality=600¦MediaType=1¦DitherType=10¦PaperKind=Letter¦PrintScaleMode=1
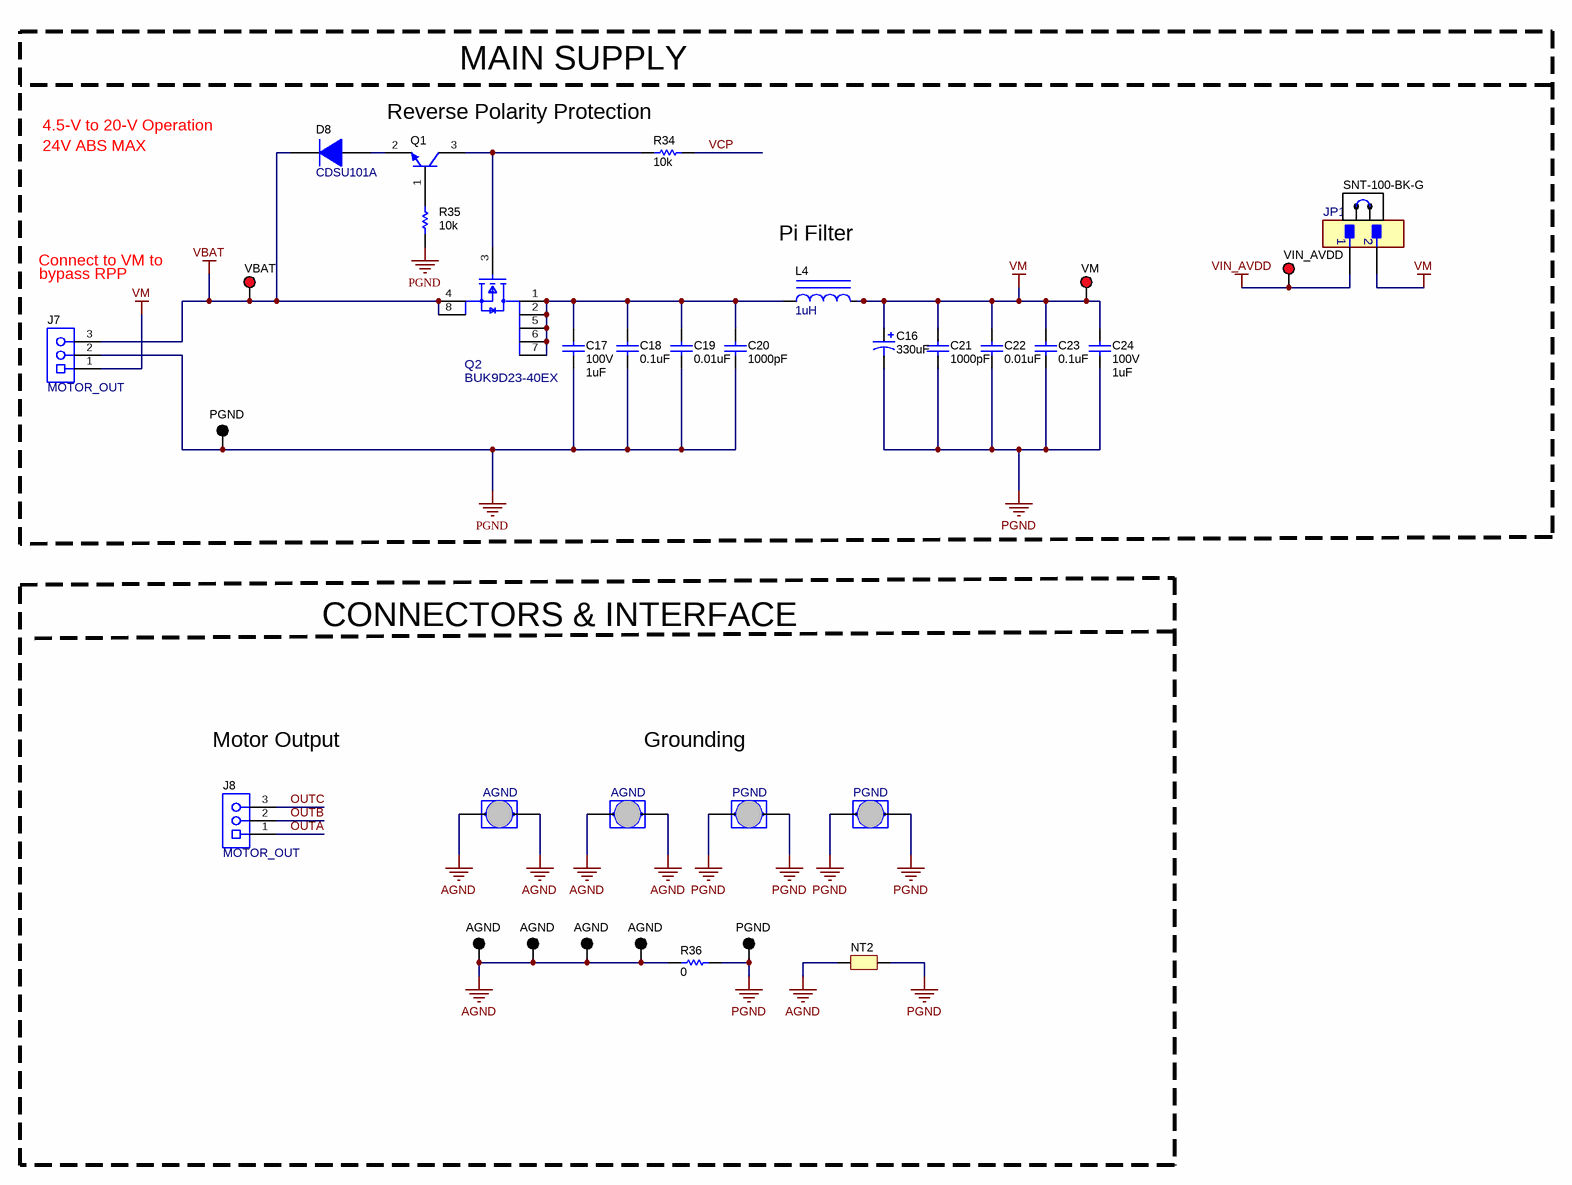
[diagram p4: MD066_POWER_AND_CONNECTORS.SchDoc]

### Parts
C16  ValueDisplayed: 330uF  [Chemi-Con_1250x2000]  (hidden comment: ELXZ630ELL331MK20S)
C17  VDC_V: 100V  ValueDisplayed: 1uF  [1206_180]  (hidden comment: CL31B105KCHNNNE)
C18  ValueDisplayed: 0.1uF  [0603L]  (hidden comment: CGA3E3X7S2A104K080AB)
C19  ValueDisplayed: 0.01uF  [0603L]  (hidden comment: CGA3E2X7R2A103K080AA)
C20  ValueDisplayed: 1000pF  [0603L]  (hidden comment: CGA3E2X7R2A102K080AA)
C21  ValueDisplayed: 1000pF  [0603L]  (hidden comment: CGA3E2X7R2A102K080AA)
C22  ValueDisplayed: 0.01uF  [0603L]  (hidden comment: CGA3E2X7R2A103K080AA)
C23  ValueDisplayed: 0.1uF  [0603L]  (hidden comment: CGA3E3X7S2A104K080AB)
C24  VDC_V: 100V  ValueDisplayed: 1uF  [1206_180]  (hidden comment: CL31B105KCHNNNE)
D8  CDSU101A  [SOD-523F]
J7  MOTOR_OUT  [On-Shore_ED120_3DS]
J8  MOTOR_OUT  [On-Shore_ED120_3DS]
JP1  VIN_AVDD_SEL  [FP-MTLW-102-07-G-S-230_HDR2-MFG]  (value not drawn)
L4  ValueDisplayed: 1uH  [SRP1038A]  (hidden comment: SRP1038A-1R0M)
NT2  Net-Tie  [Net-Tie_50milWide_30milLong]  (value not drawn)  (net tie, no BOM)
Q1  FMMT620TA  [SOT-23L]  (value not drawn)
Q2  BUK9D23-40EX  [FP-BUK9D23-40EX_SOT1220-MFG]
R34  value 10k  [0603L]  (hidden comment: CRCW060310K0JNEA)
R35  value 10k  [0603L]  (hidden comment: CRCW060310K0JNEA)
R36  ValueDisplayed: 0  [1206L]  (hidden comment: RCA12060000ZSEA)
SH-J21  SNT-100-BK-G  [SNT-100-BK-G]
TP10  VIN_AVDD  [Keystone5005]
TP23  VBAT  [Keystone5005]
TP24  VM  [Keystone5005]
TP25  PGND  [Keystone5001]
TP26  AGND  [Harwin_D3082-05]
TP27  AGND  [Harwin_D3082-05]
TP28  PGND  [Harwin_D3082-05]
TP29  PGND  [Harwin_D3082-05]
TP30  AGND  [Keystone5001]
TP31  AGND  [Keystone5001]
TP32  AGND  [Keystone5001]
TP33  AGND  [Keystone5001]
TP34  PGND  [Keystone5001]

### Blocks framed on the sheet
MAIN SUPPLY: C16-C24 D8 J7 JP1 L4 Q1 Q2 R34 R35 SH-J21 TP10 TP23-TP25
CONNECTORS & INTERFACE: J8 NT2 R36 TP26-TP34

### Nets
AGND: NT2.1 R36.1 TP26.1 TP26.2 TP27.1 TP27.2 TP30.1 TP31.1 TP32.1 TP33.1
PGND: C16.2(-) C17.2 C18.2 C19.2 C20.2 C21.2 C22.2 C23.2 C24.2 J7.2 NT2.2 R35.2 R36.2 TP25.1 TP28.1 TP28.2 TP29.1 TP29.2 TP34.1
VBAT: D8.1(K) J7.3 Q2.4(S) Q2.8(S) TP23.1
VIN_AVDD: JP1.1 TP10.1
VM: C16.1(+) C21.1 C22.1 C23.1 C24.1 J7.1 JP1.2 L4.2 TP24.1
OUTA: J8.1
OUTB: J8.2
OUTC: J8.3
VCP: R34.1
NetC17_1: C17.1 C18.1 C19.1 C20.1 L4.1 Q2.1(D) Q2.2(D) Q2.5(D) Q2.6(D) Q2.7(D)
NetD8_2: D8.2(A) Q1.2(E)
NetQ1_1: Q1.1(B) R35.1
NetQ1_3: Q1.3(C) Q2.3(G) R34.2

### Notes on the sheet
- 24V ABS MAX
- 4.5-V to 20-V Operation
- Reverse Polarity Protection
- bypass RPP
- Connect to VM to
- Pi Filter
- Motor Output
- Grounding

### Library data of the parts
C16 = CMP-0009912-2: CAP, AL, 330 uF, 63 V, +/- 20%, AEC-Q200 Grade 2, TH; Manufacturer: Chemi-Con; Polarized: Y; CompType: Capacitor; Value: 330uF; U/M: EA; Cap_F: 330µF; Value1: Unknown; VDC_V: 63V; IRMS_A: 1.29A; TaMin_C: -55°C; TaMax_C: 105°C; Cap_Case: 12.5x20mm; AEC Category: Q200; AEC Grade: 2; SizeAreaWB_mm2: 210.25; SizeArea_mm2: 156.25; SizeX_mm: 12.5; SizeZ_mm: 21.5
C17 C24 = CMP-0008801-2: CAP, CERM, 1 uF, 100 V, +/- 10%, X7R, 1206; Manufacturer: Samsung; TaMin_C: -55°C; Polarized: N; SizeAreaWB_mm2: 10.92; Value1: Unknown; U/M: EA; Value: 1uF; TaMax_C: 125°C; SizeZ_mm: 1.8; SizeX_mm: 3.2; SizeY_mm: 1.6; Cap_Case: 1206; SizeArea_mm2: 5.12; Cap_F: 1µF; AEC Category: Q200
C18 C23 = CMP-0007099-4: CAP, CERM, 0.1 uF, 100 V, +/- 10%, X7S, AEC-Q200 Grade 1, 0603; Manufacturer: TDK; Polarized: N; Value: 0.1uF; U/M: EA; Cap_F: 100nF; ESR_ohm: 0.04959; Value1: 0.04959 ohm; VDC_V: 100V; IRMS_A: 751.618mA; TaMin_C: -55°C; TaMax_C: 125°C; Cap_Case: 0603; AEC Category: Q200; AEC Qualified: Y; AEC Grade: 1; SizeAreaWB_mm2: 4.68; SizeX_mm: 1.6; SizeY_mm: 0.8; SizeArea_mm2: 1.28
C19 C22 = CMP-0007082-4: CAP, CERM, 0.01 uF, 100 V, +/- 10%, X7R, AEC-Q200 Grade 1, 0603; Manufacturer: TDK; Polarized: N; Value: 0.01uF; U/M: EA; Cap_F: 10nF; ESR_ohm: 0.235428; Value1: 0.235428 ohm; VDC_V: 100V; IRMS_A: 396.995mA; TaMin_C: -55°C; TaMax_C: 125°C; Cap_Case: 0603; AEC Category: Q200; AEC Qualified: Y; AEC Grade: 1; SizeArea_mm2: 1.28; SizeAreaWB_mm2: 4.68; SizeX_mm: 1.6; SizeY_mm: 0.8
C20 C21 = CMP-0007081-4: CAP, CERM, 1000 pF, 100 V, +/- 10%, X7R, AEC-Q200 Grade 1, 0603; Manufacturer: TDK; Polarized: N; Value: 1000pF; U/M: EA; Cap_F: 1nF; ESR_ohm: 1.97137; Value1: 1.97137 ohm; VDC_V: 100V; IRMS_A: 305.705mA; TaMin_C: -55°C; TaMax_C: 125°C; Cap_Case: 0603; AEC Category: Q200; AEC Qualified: Y; AEC Grade: 1; SizeArea_mm2: 1.28; SizeAreaWB_mm2: 4.68; SizeX_mm: 1.6; SizeY_mm: 0.8
D8 = CMP-0076943-3: Diode, Switching, 90 V, 0.1 A, SOD-523F; Manufacturer: Comchip Technology; SizeAreaWB_mm2: 5.13; Vr_V: 90V; SizeArea_mm2: 1.53; TJmax_C: 125°C; AEC Category: Q101; Value: 90V; SizeZ_mm: 0.85; Green_REACh: Incomplete; Io_A: 100mA; Vf_V: 1V; SizeY_mm: 0.9; Green_Lifecycle: Not Set; Value1: 0.1A; SizeX_mm: 1.7; MFG_Status: TI_Obsolete
J7 J8 = CMP-0074911-1: Terminal Block, 5.08 mm, 3x1, Brass, TH; Manufacturer: On-Shore Technology; PartNumber: ED120/3DS; Cert_VDE: Y; CNHeader: False; Current_A: 15A; Green_Lifecycle: Not Set; Shrouded: N; Gender: Female; Green_REACh: Incomplete; Voltage_V: 300V; Row_Count: 1; Pitch_mm: 5.08; CT: True
JP1 = CMP-0090697-1: Conn Unshrouded Header HDR 2 POS 2.54mm Solder ST Thru-Hole; Part Number: MTLW-102-07-G-S-230; Manufacturer: Samtec; Conn Gender: Male; Current_A: 5.2A; SizeZ_mm: 8.89mm; Conn Orientation: Vertical; ContactFinish: Gold,Nickel; AEC Qualified: No; Row_Count: 1
L4 = CMP-0056795-1: Inductor, Shielded, Powdered Iron, 1 uH, 18 A, 0.003 ohm, AEC-Q200 Grade 1, SMD; Manufacturer: Bourns; Isat: 36A @ 20% inductance drop; Irms: 18A @ 40C rise; Green_Lifecycle: Active; SizeAreaWB_mm2: 156; DCR_ohm: 3m; Green_REACh: Passed; Value: 1uH; Imax_A: 18A; SizeZ_mm: 4; SizeX_mm: 11; SizeY_mm: 10; SizeArea_mm2: 110; Ind_H: 1µH; AEC Qualified: Y; AEC Grade: 1; AEC Category: Q200
NT2 = CMP-0078142-4: Single point connection between nets.
Q1 = CMP-0000467-2: Transistor, NPN, 80 V, 1.5 A, AEC-Q101, SOT-23; Manufacturer: Diodes Inc.; TaMax_C: 150°C; Value2: 900; Value1: 1.5 A; Vcesat1_V: 160mV; SizeX_mm: 2.5; SizeY_mm: 3; TaMin_C: -55°C; IcRated_A: 1.5A; CompType: BJT; SizeZ_mm: 1.1; AEC Qualified: Y; Value: 80 V; SizeArea_mm2: 7.5; NPN: 1; Vceo_V: 80V; PNP: 0; AEC Category: Q101; SizeAreaWB_mm2: 14; U/M: EA
Q2 = CMP-0088880-1: N-Channel 40V 8A (Ta) 15W (Tc) Surface Mount DFN2020MD-6; Manufacturer: Nexperia; Reverse Recovery Charge: 5.3nC; Vgs_V: 15V; Rthja Max: 57K/W; Number Of N Channels: 1; Pulse Drain Current: 76A; Threshold Vgs Max: 2.1V; Power_W: 2.3W; Reverse Recovery Time: 12.9ns; TaMin_C: -55°C; Rdson45_ohm: 0.018; SizeZ_mm: 0.65mm; ChMode: False; Transconductance: 39S; AEC Qualified: Yes; Typ Forward Diode Voltage: 0.8V; Turn Off Delay Time: 12ns; TaMax_C: +175°C; Input Capacitace At Vds: 637pF @ 20V; QgTyp_nC: 11.5nC @ 10V; Threshold Vgs Min: 1.4V; AEC Grade: Grade 0; VdsMax_V: 1.2V; Turn On Delay Time: 2ns
R34 R35 = CMP-0025701-4: RES, 10 k, 5%, 0.1 W, AEC-Q200 Grade 0, 0603; Manufacturer: Vishay-Dale; Value_Code: 10k0; Power_W: 100mW; Value2: 0.1W; VDC_V: 75V; TempCo: 200 ppm/C; EIA_Code: E24; AEC Category: Q200; AEC Qualified: Y; AEC Grade: 0; SizeArea_mm2: 1.28; SizeX_mm: 1.6; SizeY_mm: 0.8; SizeZ_mm: 1
R36 = CMP-0018760-2: RES, 0, 5%, 0.25 W, AEC-Q200 Grade 0, 1206; Manufacturer: Vishay-Dale; Power_W: 250mW; TempCo: ppm/C; Value_Code: 0000; U/M: EA; Value: 0; EIA_Code: E24; SizeX_mm: 3.2; SizeY_mm: 1.6; SizeZ_mm: 1.35; Value2: 0.25W; SizeArea_mm2: 5.12; AEC Qualified: Y; AEC Category: Q200
SH-J21 = CMP-0003623-3: as SH-J1 on sheet MD066_CONTROL
TP10 TP23 TP24 = CMP-0055142-1: Test Point, Compact, Red, TH; Manufacturer: Keystone; CNHeader: FALSE; ContactFinish: Silver; CT: TRUE; Green_Lifecycle: Active; Green_REACh: Passed
TP25 TP30-TP34 = CMP-0055138-1: Test Point, Miniature, Black, TH; Manufacturer: Keystone; CNHeader: FALSE; Green_Lifecycle: Active; Green_REACh: Passed; ContactFinish: Silver; CT: TRUE
TP26-TP29 = CMP-0075110-1: 1mm Uninsulated Shorting Plug, 10.16mm spacing, TH; Manufacturer: Harwin; PartNumber: D3082-05; CNHeader: False; Green_Lifecycle: Active; Green_REACh: Passed; CompType: Jumper Wire

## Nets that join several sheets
AGND: MD066_CONTROL (C2.2 R4.3 R6.1 R7.1), MD066_DRIVER (15 pins), MD066_INTERFACE (25 pins), MD066_POWER_AND_CONNECTORS (10 pins)
AVDD: MD066_CONTROL (R1.2 R2.2 R4.1), MD066_DRIVER (9 pins)
PGND: MD066_DRIVER (7 pins), MD066_POWER_AND_CONNECTORS (19 pins)
VIN_AVDD: MD066_DRIVER (U1.7), MD066_POWER_AND_CONNECTORS (JP1.1 TP10.1)
VM: MD066_DRIVER (8 pins), MD066_POWER_AND_CONNECTORS (9 pins)
ALARM: MD066_DRIVER (D3.1 R30.1 U1.35), MD066_INTERFACE (J6.9)
BRAKE: MD066_DRIVER (U1.31), MD066_INTERFACE (J6.27)
BRAKE_SW: MD066_CONTROL (S1.2 TP2.1), MD066_INTERFACE (J6.28)
DACOUT1: MD066_DRIVER (R28.1 TP15.1 U1.34), MD066_INTERFACE (J6.11)
DACOUT2: MD066_DRIVER (R29.1 TP16.1 U1.33), MD066_INTERFACE (J6.13)
DACOUT2/SOX: MD066_DRIVER (R27.1 TP17.1 U1.32), MD066_INTERFACE (J6.15)
DIR: MD066_DRIVER (U1.28), MD066_INTERFACE (J6.29)
DIR_SW: MD066_CONTROL (S2.2 TP3.1), MD066_INTERFACE (J6.30)
FG: MD066_DRIVER (R10.1 TP35.1 U1.25), MD066_INTERFACE (J6.5)
MCX_SCL: MD066_DRIVER (R13.1 R15.1), MD066_INTERFACE (J6.23)
MCX_SDA: MD066_DRIVER (R14.1 R16.1), MD066_INTERFACE (J6.21)
MSP_TB0.1: MD066_CONTROL (J1.6), MD066_INTERFACE (U4.42)
nFAULT: MD066_DRIVER (R18.1 U1.36), MD066_INTERFACE (J6.7)
OUTA: MD066_DRIVER (TP5.1 U1.11 U1.12), MD066_POWER_AND_CONNECTORS (J8.1)
OUTB: MD066_DRIVER (TP6.1 U1.14 U1.15), MD066_POWER_AND_CONNECTORS (J8.2)
OUTC: MD066_DRIVER (TP9.1 U1.17 U1.18), MD066_POWER_AND_CONNECTORS (J8.3)
POT: MD066_CONTROL (C2.1 J1.4 R9.1), MD066_INTERFACE (U4.43)
SPEED/WAKE: MD066_DRIVER (TP14.1 U1.24), MD066_INTERFACE (J6.25)
SPEED_IN: MD066_CONTROL (J1.1 J1.3 J1.5), MD066_INTERFACE (J6.26)
VCP: MD066_DRIVER (C1.1 TP13.1 U1.6), MD066_POWER_AND_CONNECTORS (R34.1)

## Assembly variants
001: not fitted R21 R22 R23 R24 R27 R28 R29 R30
002: all parts fitted
003: all parts fitted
